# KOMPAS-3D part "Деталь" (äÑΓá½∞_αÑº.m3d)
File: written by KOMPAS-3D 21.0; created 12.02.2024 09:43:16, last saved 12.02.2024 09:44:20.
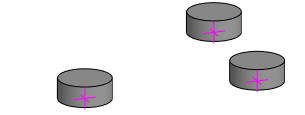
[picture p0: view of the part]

Document properties: Автор: alg; Полное имя файла: C:\Деталь_рез.m3d

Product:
- Part/product: Деталь

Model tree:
1. Эскиз:1
2. Элемент выдавливания:1
     Расстояние 1 = 10
3. Эскиз:2
4. Тело без истории:1
5. Тело без истории:2
6. Тело без истории:3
